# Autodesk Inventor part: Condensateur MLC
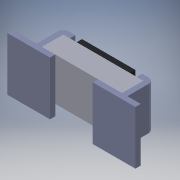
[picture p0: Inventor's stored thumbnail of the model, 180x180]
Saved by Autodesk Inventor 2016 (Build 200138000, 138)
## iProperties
Created: 2018-03
Part Number: Condensateur MLC
Material: Générique
Document SubType Name: Modeling
Designer: Bruno
Density: 1 g/cm^3
Appearance: Par défaut
Author: Bruno
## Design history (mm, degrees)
feature "Composite1"
body "Srf1"
